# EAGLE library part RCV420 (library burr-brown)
Precision 4mA to 20mA CURRENT LOOP RECEIVER Source: http://focus.ti.com/lit/ds/symlink/rcv420.pdf
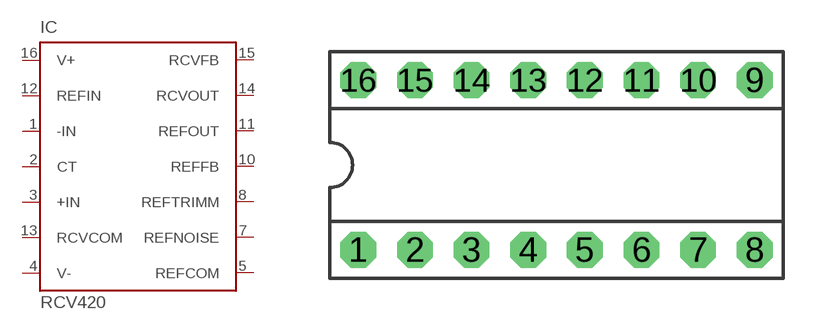
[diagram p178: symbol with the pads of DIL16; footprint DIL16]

Designator prefix IC

## RCV420P (MF: TEXAS INSTRUMENTS; MPN: RCV420JP; OC_FARNELL: 1212342; OC_NEWARK: 60K6765)  [DIL16]
1  -IN  in
2  CT  in
3  +IN  in
4  V-  in
5  REFCOM  in
7  REFNOISE  in
8  REFTRIMM  in
10  REFFB  in
11  REFOUT  out
12  REFIN  in
13  RCVCOM  in
14  RCVOUT  out
15  RCVFB  in
16  V+  in

## Footprint DIL16 (pad centres in mm)
Dual In Line
drill 0.813 pad 1.6 octagon: 1 -8.89,-3.81; 2 -6.35,-3.81; 3 -3.81,-3.81; 4 -1.27,-3.81; 5 1.27,-3.81; 6 3.81,-3.81; 7 6.35,-3.81; 8 8.89,-3.81; 9 8.89,3.81; 10 6.35,3.81; 11 3.81,3.81; 12 1.27,3.81; 13 -1.27,3.81; 14 -3.81,3.81; 15 -6.35,3.81; 16 -8.89,3.81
